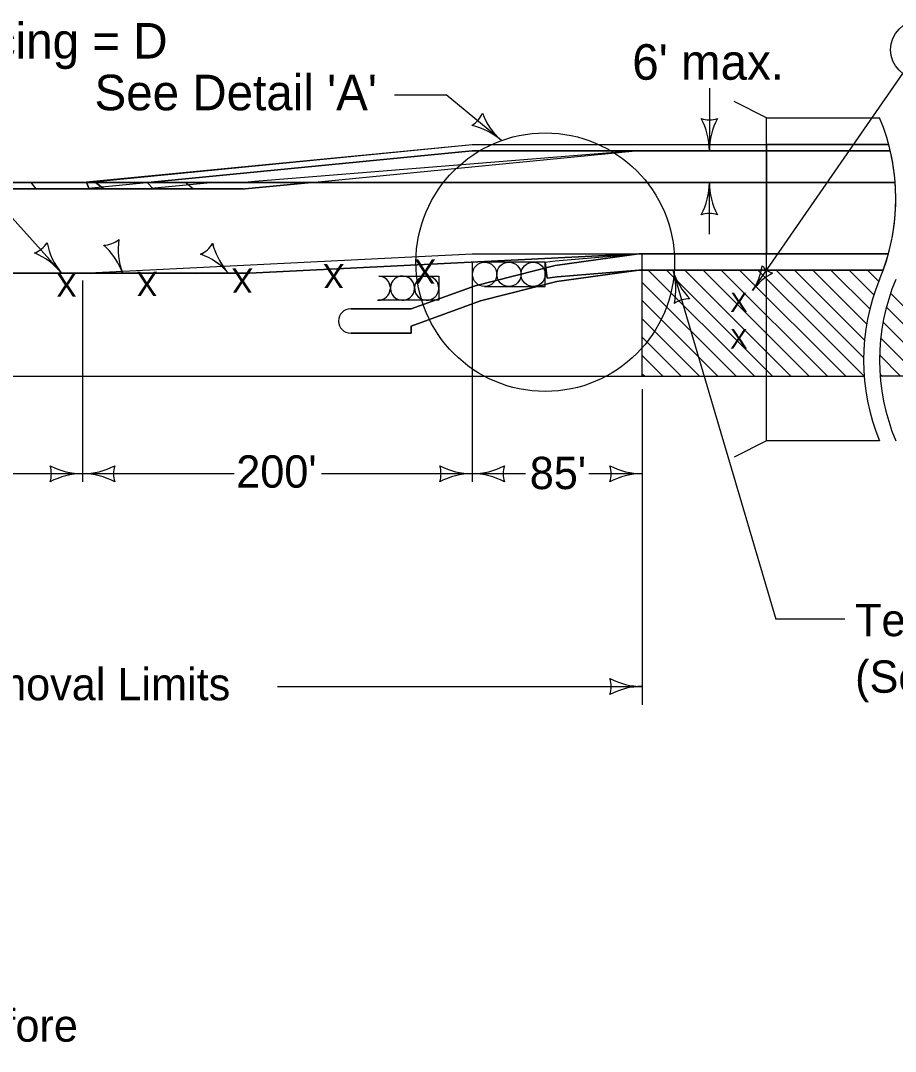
# Model space of a CAD drawing. Extents: x 10133 to 2270741, y 5363 to 1733450.
# Drawn here: x 30154 to 30695, y 11275 to 11913 of the extents above; entities that cross this region are included whole.
import ezdxf

# ---------------------------------------------------------------- set-up
doc = ezdxf.new("R2010")
doc.units = 0
for name, color, linetype in [('dsnNonPlotable', 7, 'Continuous'), ('dsnShtPlotShapeBatchPrint', 7, 'Continuous'), ('dsnStdBlockModified', 7, 'Continuous'), ('dsnStdBorder', 7, 'Continuous'), ('Level 12', 7, 'Continuous'), ('Level 2', 7, 'Continuous')]:
    doc.layers.add(name, color=color, linetype=linetype)

# ---------------------------------------------------------------- blocks, each defined once
blk = doc.blocks.new('LT')
at = {"layer": 'dsnStdBorder'}
for centre, radius, start, end in [((-3.564, 0), 1.642, 342.26665, 17.73335), ((0, 4.25), 4.25, 241.92751, 270), ((0, -4.25), 4.25, 90, 118.07249)]:
    blk.add_arc(centre, radius, start, end, dxfattribs=at)

msp = doc.modelspace()

# ---------------------------------------------------------------- linework, layer by layer
at = {"layer": 'dsnNonPlotable'}
for p, q in [((30615.21, 11852.62), (30595.21, 11862.62)), ((30191.35, 11808.62), (30433.01, 11832.12)), ((30433.01, 11832.12), (30691.82, 11832.12)), ((30534.24, 11832.12), (30691.85, 11832.12)), ((30194.51, 11812.62), (30517.18, 11812.62)), ((30517.18, 11812.62), (30694.83, 11812.62)), ((30191.96, 11756.35), (30433.01, 11768.35)), ((30433.01, 11768.35), (30536.32, 11768.35)), ((30690.62, 11768.35), (30664.27, 11768.35)), ((30043.77, 11756.35), (30191.96, 11756.35)), ((30661.1, 11758.35), (30687.45, 11758.35)), ((30615.21, 11652.62), (30595.21, 11642.62))]:
    msp.add_line(p, q, dxfattribs=at)
for points in [[(30685.21, 11652.62), (30615.21, 11652.62), (30615.21, 11852.62), (30685.21, 11852.62)], [(28161.75, 11808.62), (30191.35, 11808.62)], [(30478.33, 11763.23), (30484.41, 11764.02), (30536.32, 11768.35)], [(30478.33, 11763.23), (30479.59, 11753.39), (30479.59, 11753.39)], [(30690.62, 11768.35), (30536.32, 11768.35)], [(30479.59, 11753.39), (30485.67, 11754.18), (30536.32, 11758.35)], [(30536.32, 11758.35), (30687.45, 11758.35)]]:
    msp.add_lwpolyline(points, dxfattribs=at)
for centre, start, end in [((30565.21, 11802.62), 337.38013, 22.61986), ((30805.21, 11702.62), 157.38013, 202.61986), ((30815.21, 11702.62), 157.38013, 202.61986)]:
    msp.add_arc(centre, 130, start, end, dxfattribs=at)
at = {"layer": 'dsnShtPlotShapeBatchPrint'}
msp.add_circle((30709.93, 11894.73), 18, dxfattribs=at)
at = {"layer": 'dsnStdBlockModified'}
for p, q in [((30478.33, 11763.23), (30440.82, 11763.23)), ((30478.33, 11748.23), (30478.33, 11763.23)), ((30440.82, 11748.23), (30478.33, 11748.23))]:
    msp.add_line(p, q, dxfattribs=at)
for centre in [(30440.82, 11755.73), (30440.82, 11755.73), (30455.82, 11755.73), (30455.82, 11755.73), (30470.83, 11755.73), (30470.83, 11755.73)]:
    msp.add_circle(centre, 7.5, dxfattribs=at)
at = {"layer": 'dsnStdBorder'}
for p, q in [((30538.28, 11692.62), (30538.28, 11758.35)), ((30541.98, 11758.35), (30607.72, 11692.62)), ((30553.3, 11758.35), (30619.03, 11692.62)), ((30564.61, 11758.35), (30630.35, 11692.62)), ((30575.93, 11758.35), (30641.66, 11692.62)), ((30587.24, 11758.35), (30652.97, 11692.62)), ((30598.55, 11758.35), (30664.29, 11692.62)), ((30609.87, 11758.35), (30649.83, 11718.39)), ((30621.18, 11758.35), (30675.23, 11704.3)), ((30632.49, 11758.35), (30675.81, 11715.04)), ((30643.81, 11758.35), (30677.16, 11725)), ((30655.12, 11758.35), (30679.14, 11734.33)), ((30666.44, 11758.35), (30681.68, 11743.11)), ((30677.75, 11758.35), (30684.71, 11751.39)), ((30538.28, 11750.74), (30596.4, 11692.62)), ((30692.01, 11744.09), (30743.48, 11692.62)), ((30538.28, 11739.43), (30585.09, 11692.62)), ((30689.41, 11735.38), (30732.17, 11692.62)), ((30538.28, 11728.12), (30573.78, 11692.62)), ((30687.36, 11726.12), (30720.86, 11692.62)), ((30649.83, 11718.39), (30675.6, 11692.62)), ((30538.28, 11716.8), (30562.46, 11692.62)), ((30685.93, 11716.23), (30709.54, 11692.62)), ((30538.28, 11705.49), (30551.15, 11692.62)), ((30685.25, 11705.6), (30698.23, 11692.62)), ((30538.28, 11694.18), (30539.84, 11692.62)), ((30649.05, 11696.58), (30653.01, 11692.62)), ((30685.5, 11694.03), (30686.91, 11692.62))]:
    msp.add_line(p, q, dxfattribs=at)
for centre, radius in [((30478.33, 11763.23), 80), ((30440.82, 11755.73), 7.5), ((30455.82, 11755.73), 7.5), ((30470.83, 11755.73), 7.5)]:
    msp.add_circle(centre, radius, dxfattribs=at)
at = {"layer": 'Level 12'}
for p, q in [((30178.91, 11756.7), (30050.14, 11899.71)), ((30606.63, 11745.63), (30699.65, 11879.95)), ((30579.86, 11870.88), (30579.86, 11832.12)), ((30384.96, 11866.84), (30416.96, 11866.84)), ((30451.24, 11838.51), (30416.96, 11866.84)), ((30570.05, 11832.12), (30587.86, 11832.12)), ((30569.04, 11812.62), (30587.86, 11812.62)), ((30579.86, 11780.62), (30579.86, 11812.62)), ((30433.01, 11763.5), (30433.01, 11627.39)), ((30557.36, 11758.35), (30620.89, 11542.33)), ((30191.96, 11751.92), (30191.96, 11627.39)), ((30538.28, 11684.62), (30538.28, 11489.25)), ((30285.77, 11632.3), (30133.57, 11632.3)), ((30433.07, 11632.3), (30339.93, 11632.3)), ((30466.07, 11632.3), (30433.07, 11632.3)), ((30538.34, 11632.3), (30505.34, 11632.3)), ((30663.73, 11542.33), (30620.89, 11542.33)), ((30312.59, 11500.66), (30538.28, 11500.66))]:
    msp.add_line(p, q, dxfattribs=at)
for centre, radius, start, end in [((30424.37, 11861.91), 16.42, 301.22013, 336.68683), ((30479.15, 11870.56), 42.5, 200.88099, 228.95348), ((30579.86, 11867.76), 16.42, 252.26665, 287.73335), ((30537.36, 11832.12), 42.5, 0, 28.07249), ((30622.36, 11832.12), 42.5, 151.92751, 180), ((30423.33, 11806.46), 42.5, 48.95348, 77.02597), ((30537.36, 11812.62), 42.5, 331.92751, 0), ((30622.36, 11812.62), 42.5, 180, 208.07249), ((30579.86, 11776.98), 16.42, 72.26665, 107.73335), ((30156.28, 11784.18), 16.42, 291.6303, 327.097), ((30211.74, 11783.59), 42.5, 191.29116, 219.36365), ((30146.02, 11729.68), 42.5, 39.36365, 67.43614), ((30516.59, 11746.36), 42.5, 348.31445, 16.38694), ((30598.14, 11770.34), 42.5, 196.38694, 224.45943), ((30567.42, 11724.16), 16.42, 88.65359, 124.12029), ((30156.32, 11632.3), 16.42, 342.26665, 17.73335), ((30191.96, 11674.8), 42.5, 241.92751, 270), ((30191.96, 11674.8), 42.5, 270, 298.07249), ((30227.59, 11632.3), 16.42, 162.26665, 197.73335), ((30397.44, 11632.3), 16.42, 342.26665, 17.73335), ((30433.07, 11674.8), 42.5, 241.92751, 270), ((30433.07, 11674.8), 42.5, 270, 298.07249), ((30468.71, 11632.3), 16.42, 162.26665, 197.73335), ((30502.7, 11632.3), 16.42, 342.26665, 17.73335), ((30538.34, 11674.8), 42.5, 241.92751, 270), ((30191.96, 11589.8), 42.5, 90, 118.07249), ((30191.96, 11589.8), 42.5, 61.92751, 90), ((30433.07, 11589.8), 42.5, 90, 118.07249), ((30433.07, 11589.8), 42.5, 61.92751, 90), ((30538.34, 11589.8), 42.5, 90, 118.07249), ((30502.64, 11500.66), 16.42, 342.26665, 17.73335), ((30538.28, 11543.16), 42.5, 241.92751, 270), ((30538.28, 11458.16), 42.5, 90, 118.07249)]:
    msp.add_arc(centre, radius, start, end, dxfattribs=at)
at = {"layer": 'Level 2'}
for p, q in [((30190.18, 11812.51), (30433.01, 11836.12)), ((30194.51, 11812.62), (30433.01, 11836.12)), ((30433.01, 11836.12), (30690.81, 11836.12)), ((30433.01, 11836.12), (30579.67, 11836.12)), ((30580.05, 11836.12), (30615.21, 11836.12)), ((30615.21, 11836.12), (30615.21, 11832.12)), ((30615.21, 11836.12), (30615.21, 11832.12)), ((30664.48, 11836.12), (30690.88, 11836.12)), ((30433.01, 11832.12), (30232.46, 11812.62)), ((30232.46, 11812.62), (30433.01, 11832.12)), ((30534.24, 11832.12), (30298.68, 11813.23)), ((30333.69, 11812.62), (30534.24, 11832.12)), ((30579.86, 11832.12), (30433.01, 11832.12)), ((30433.01, 11832.12), (30570.05, 11832.12)), ((30570.05, 11832.12), (30579.86, 11832.12)), ((30587.86, 11832.12), (30579.86, 11832.12)), ((30579.86, 11832.12), (30587.86, 11832.12)), ((30615.21, 11832.12), (30587.86, 11832.12)), ((30587.86, 11832.12), (30615.21, 11832.12)), ((30691.82, 11832.12), (30615.21, 11832.12)), ((30615.21, 11832.12), (30615.21, 11812.62)), ((30615.21, 11832.12), (30615.21, 11812.62)), ((30615.21, 11832.12), (30691.82, 11832.12)), ((28165.75, 11812.62), (30292.37, 11812.62)), ((30194.51, 11812.62), (29984.08, 11812.62)), ((29987.32, 11808.62), (30196.1, 11808.62)), ((30196.1, 11808.62), (29987.32, 11808.62)), ((30163.25, 11808.62), (30160.32, 11812.62)), ((30160.32, 11812.62), (30200.06, 11812.62)), ((30205.11, 11808.62), (30163.25, 11808.62)), ((30196.1, 11808.62), (30194.51, 11812.62)), ((30232.46, 11812.62), (30194.51, 11812.62)), ((30255.56, 11812.62), (30194.51, 11812.62)), ((30194.51, 11812.62), (30196.1, 11808.62)), ((30196.1, 11808.62), (30260.4, 11808.62)), ((30235.66, 11808.62), (30196.1, 11808.62)), ((30200.06, 11812.62), (30205.11, 11808.62)), ((30205.11, 11808.62), (30200.06, 11812.62)), ((30200.06, 11812.62), (30231.62, 11812.62)), ((30232.2, 11808.62), (30205.11, 11808.62)), ((30231.62, 11812.62), (30273.48, 11812.62)), ((30232.07, 11812.62), (30235.66, 11808.62)), ((30273.48, 11812.62), (30232.2, 11808.62)), ((30517.18, 11812.62), (30232.46, 11812.62)), ((30260.4, 11808.62), (30255.56, 11812.62)), ((30298.68, 11813.23), (30292.37, 11812.62)), ((30292.37, 11812.62), (30333.69, 11812.62)), ((30292.57, 11808.62), (30333.69, 11812.62)), ((30517.18, 11812.62), (30333.69, 11812.62)), ((30569.04, 11812.62), (30517.18, 11812.62)), ((30579.86, 11812.62), (30569.04, 11812.62)), ((30579.86, 11793.4), (30579.86, 11812.62)), ((30615.21, 11812.62), (30694.83, 11812.62)), ((30694.83, 11812.62), (30615.21, 11812.62)), ((30615.21, 11812.62), (30615.21, 11768.35)), ((30615.21, 11768.35), (30615.21, 11812.62)), ((30536.32, 11768.35), (30295.26, 11756.35)), ((30295.26, 11756.35), (30536.32, 11768.35)), ((30479.59, 11753.39), (30478.33, 11763.23)), ((30538.28, 11768.45), (30536.32, 11768.35)), ((30536.32, 11768.35), (30690.62, 11768.35)), ((30536.32, 11768.35), (30615.21, 11768.35)), ((30538.28, 11758.35), (30538.28, 11768.45)), ((30615.21, 11768.35), (30690.62, 11768.35)), ((30262.47, 11756.35), (30147.08, 11756.35)), ((30147.08, 11756.35), (30295.26, 11756.35)), ((30215.87, 11758.72), (30216.67, 11756.69)), ((30295.26, 11756.35), (30262.47, 11756.35)), ((30262.72, 11756.02), (30262.47, 11756.35)), ((30280.54, 11758.57), (30282.21, 11756.7)), ((30282.22, 11756.69), (30280.55, 11758.56)), ((30687.45, 11758.35), (30536.32, 11758.35)), ((30538.28, 11692.62), (30538.28, 11758.35)), ((30375.34, 11754.68), (30389.91, 11754.68)), ((30390.35, 11754.68), (30405.35, 11754.68)), ((30405.35, 11754.68), (30412.46, 11754.68)), ((30412.46, 11754.68), (30412.46, 11747.18)), ((30412.46, 11746.79), (30412.46, 11739.68)), ((30389.56, 11739.68), (30374.95, 11739.68)), ((30404.57, 11739.68), (30389.56, 11739.68)), ((30412.46, 11739.68), (30404.57, 11739.68)), ((30357.93, 11734.34), (30395.44, 11734.34)), ((30395.44, 11734.34), (30357.93, 11734.34)), ((30395.44, 11719.34), (30357.93, 11719.34)), ((30357.93, 11719.34), (30395.44, 11719.34)), ((30395.44, 11719.34), (30395.44, 11723.7)), ((28165.75, 11692.62), (30497.95, 11692.62)), ((29595.49, 11692.62), (30426.14, 11692.62)), ((30426.14, 11692.62), (30675.6, 11692.62)), ((30855.98, 11692.62), (30685.6, 11692.62))]:
    msp.add_line(p, q, dxfattribs=at)
for points in [[(30690.81, 11836.12), (30664.48, 11836.12), (30615.21, 11836.12)], [(30690.82, 11836.13), (30690.81, 11836.12)], [(30333.69, 11812.62), (30292.37, 11812.62), (30232.07, 11812.62)], [(30235.66, 11808.62), (30291.61, 11808.62), (30292.57, 11808.62)], [(30291.61, 11808.62), (30287.3, 11808.62), (30235.66, 11808.62)], [(30333.69, 11812.62), (30292.57, 11808.62), (30291.61, 11808.52)], [(30291.61, 11808.52), (30291.61, 11808.62)], [(30615.21, 11812.62), (30587.86, 11812.62), (30579.86, 11812.62), (30569.04, 11812.62), (30517.18, 11812.62)], [(30615.21, 11812.62), (30587.86, 11812.62), (30579.86, 11812.62)], [(30395.44, 11734.34), (30434.87, 11748.69), (30484.39, 11761.1), (30536.32, 11768.35)], [(30536.32, 11768.35), (30484.39, 11761.1), (30434.87, 11748.69), (30395.44, 11734.34)], [(30478.33, 11763.23), (30484.41, 11764.02), (30535.97, 11768.32), (30536.32, 11768.35)], [(30536.32, 11768.35), (30536.32, 11768.35)], [(30216.67, 11756.7), (30216.67, 11756.7), (30215.86, 11758.73)], [(30216.67, 11756.69), (30216.67, 11756.7)], [(30282.21, 11756.7), (30282.18, 11756.63)], [(30282.18, 11756.63), (30282.22, 11756.69)], [(30538.28, 11758.35), (30536.32, 11758.35), (30485.57, 11751.22), (30438.29, 11739.3), (30395.44, 11723.7)], [(30395.44, 11723.7), (30438.29, 11739.3), (30485.57, 11751.22), (30536.32, 11758.35), (30538.28, 11758.35)], [(30536.32, 11758.35), (30485.67, 11754.18), (30479.59, 11753.39)], [(30375.34, 11754.67), (30375.34, 11754.68)], [(30390.35, 11754.67), (30390.35, 11754.68)], [(30405.35, 11754.67), (30405.35, 11754.68)], [(30405.35, 11754.68), (30405.35, 11754.67)], [(30382.44, 11746.79), (30382.46, 11746.79)], [(30397.45, 11746.79), (30397.47, 11746.79)], [(30412.45, 11746.79), (30412.46, 11746.79)], [(30389.56, 11739.69), (30389.56, 11739.68)], [(30389.56, 11739.68), (30389.56, 11739.69)], [(30404.57, 11739.69), (30404.57, 11739.68)], [(30404.57, 11739.68), (30404.57, 11739.69)], [(30395.44, 11723.7), (30395.44, 11723.7), (30395.44, 11719.34)], [(30426.14, 11692.62), (30497.95, 11692.62), (30538.28, 11692.62)]]:
    msp.add_lwpolyline(points, dxfattribs=at)
for centre, radius, start, end in [((30537.36, 11832.12), 42.5, 0, 5.40055), ((30622.36, 11832.12), 42.5, 174.59945, 179.9824), ((30565.21, 11802.62), 130, 13.11835, 14.93711), ((30537.36, 11832.12), 42.5, 0, 0.0176), ((30565.21, 11802.62), 130, 4.41173, 13.11835), ((30537.36, 11812.62), 42.5, 331.92751, 0), ((30565.21, 11802.62), 130, 344.71769, 4.41173), ((30579.86, 11776.98), 16.42, 90, 107.73335), ((30204.4, 11790.16), 16.42, 272.4117, 307.87841), ((30204.4, 11790.15), 16.42, 272.4117, 307.87841), ((30256.57, 11771.34), 42.5, 172.07256, 200.12745), ((30256.57, 11771.33), 42.5, 172.07256, 200.12745), ((30176.77, 11742.07), 42.5, 23.08987, 48.21754), ((30176.77, 11742.06), 42.5, 23.08987, 48.21754), ((30258.35, 11783.13), 16.42, 294.23038, 329.69708), ((30258.36, 11783.12), 16.42, 294.23038, 329.69708), ((30313.78, 11785.05), 42.5, 193.89124, 218.54149), ((30313.79, 11785.04), 42.5, 193.89124, 218.54149), ((30250.58, 11728.21), 42.5, 41.98133, 70.03621), ((30250.59, 11728.2), 42.5, 41.98133, 70.03621), ((30565.21, 11802.62), 130, 340.09277, 344.71769), ((30176.77, 11742.07), 42.5, 20.14505, 20.16266), ((30297.06, 11781.06), 42.5, 215.53894, 216.08181), ((30228.38, 11730.98), 42.5, 36.09942, 36.11702), ((30297.06, 11781.06), 42.5, 216.09886, 216.09942), ((30313.78, 11785.05), 42.5, 221.94612, 221.96373), ((30374.93, 11747.14), 7.55, 3.31891, 86.85969), ((30374.95, 11747.18), 7.5, 42.02925, 86.99754), ((30374.93, 11747.14), 7.55, 3.33369, 42.17238), ((30389.96, 11747.18), 7.5, 267, 266.95518), ((30389.96, 11747.18), 7.5, 90.32252, 176.98686), ((30389.93, 11747.13), 7.55, 3.32299, 86.85561), ((30389.96, 11747.18), 7.5, 40.94586, 87.00017), ((30389.93, 11747.13), 7.55, 3.4004, 41.09796), ((30404.96, 11747.18), 7.5, 86.99578, 177.00422), ((30404.96, 11747.18), 7.5, 86.99754, 176.91872), ((30404.96, 11747.18), 7.5, 356.99981, 87.00019), ((30404.96, 11747.18), 7.5, 0, 86.99754), ((30374.95, 11747.18), 7.5, 267.00007, 356.99993), ((30374.95, 11747.18), 7.5, 270, 357.00426), ((30389.96, 11747.18), 7.5, 182.98758, 266.95828), ((30389.96, 11747.18), 7.5, 267.0031, 357.00426), ((30404.96, 11747.18), 7.5, 177.00604, 266.99396), ((30404.96, 11747.18), 7.5, 182.98758, 267.0031), ((30404.95, 11747.19), 7.51, 267.1005, 356.8995), ((30404.96, 11747.18), 7.5, 267.0031, 357.00407), ((30357.93, 11726.84), 7.5, 90, 270), ((30357.93, 11726.84), 7.5, 90, 270)]:
    msp.add_arc(centre, radius, start, end, dxfattribs=at)

# ---------------------------------------------------------------- block references
at = {"layer": 'Level 12', "xscale": 7.999600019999, "yscale": 7.999200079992, "rotation": -124.70293665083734}
msp.add_blockref('LT', (30606.63, 11745.63), dxfattribs=at)

# ---------------------------------------------------------------- texts
at = {"layer": 'dsnStdBorder'}
for p in [(30410.66, 11764.98), (30188.83, 11756.92), (30238.58, 11757.41), (30297.61, 11759.38), (30354.14, 11762.18)]:
    msp.add_text('X', height=15, rotation=180, dxfattribs=at).set_placement(p)
for p in [(30592.77, 11732.47), (30592.77, 11709.82)]:
    msp.add_text('X', height=12, dxfattribs=at).set_placement(p)
at = {"layer": 'Level 12'}
for s, height, p in [('Spacing = D', 22, (30083.56, 11889.25)), ("6' max.", 22, (30532.16, 11876.15)), ("See Detail 'A'", 22, (30199.42, 11857.26)), ("200'", 20, (30287.12, 11623.71)), ("85'", 20, (30468.74, 11622.81)), ('Temporary Barrier Rail', 20, (30670.05, 11531.8)), ('(See Typical 8210)', 20, (30670.05, 11496.8)), ('Pavement Marking Removal Limits', 20, (29870.25, 11492.14)), ('Move Merge signs before', 20, (29887.38, 11280.9))]:
    msp.add_text(s, height=height, dxfattribs=at).set_placement(p)

doc.saveas('drawing.dxf')
